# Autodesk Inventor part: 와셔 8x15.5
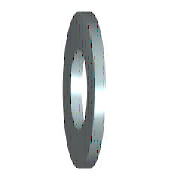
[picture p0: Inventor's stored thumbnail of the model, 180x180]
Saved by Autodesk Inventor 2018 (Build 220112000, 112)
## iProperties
Created: 2012-02
Part Number: 와셔 8x15.5
Material: 강철, 연강
Description: 평면 와셔
Document SubType Name: Modeling
Standard: KS B 1326
Designer: mduedu
Standards Organization: KS
Language: ko-KR
Size Designation: 8x15.5
Categories: <MemberInstance><Categories><Category DisplayName="조임쇠" InternalName="e4da775c-781d-43d5-af7c-5136215cf5a6" Mnemonic="FSTN"><Category DisplayName="와셔" InternalN
Density: 7.86 g/cm^3
Mass: 1.67606 g
Surface Area: 3.86683 cm^2
Volume: 0.213239 cm^3
Appearance: 노란색
IsCustomPart: 1
Author: mduedu
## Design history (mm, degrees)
sketch "스케치"
  geometry: C1 r 7.75 at (0, 0); C2 r 4.2 at (0, 0); 1 further point
  constraints: 2 centre point, 2 coincident
  dimensions: "d0" = 8.4 diameter of C2 (= SD1); "d1" = 15.5 diameter of C1 (= SD2)
extrude "본체" new body sketch "스케치" distance "d2" = 1.6 (= SD); taper "d3" = 0 deg
workaxis "Work Axis1"
workplane "Work Plane1"
body "Solid1"
other parameters: "SD1" = 8.4 [user parameter; used in 1 equation term], "SD2" = 15.5 [user parameter; used in 1 equation term], "SD" = 1.6 [user parameter; used in 1 equation term], "d4" = 0, "d5" = 0, "d6" = 0, "d7" = 0, "NND" = 8 [user parameter]
